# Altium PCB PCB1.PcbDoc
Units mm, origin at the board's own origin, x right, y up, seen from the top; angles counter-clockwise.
Board outline 33.4 x 71.75 mm, 2 copper layers (Top Layer, Bottom Layer), stack 1.586 mm thick; 24 components, 15 nets, 88 pads, 22 vias.
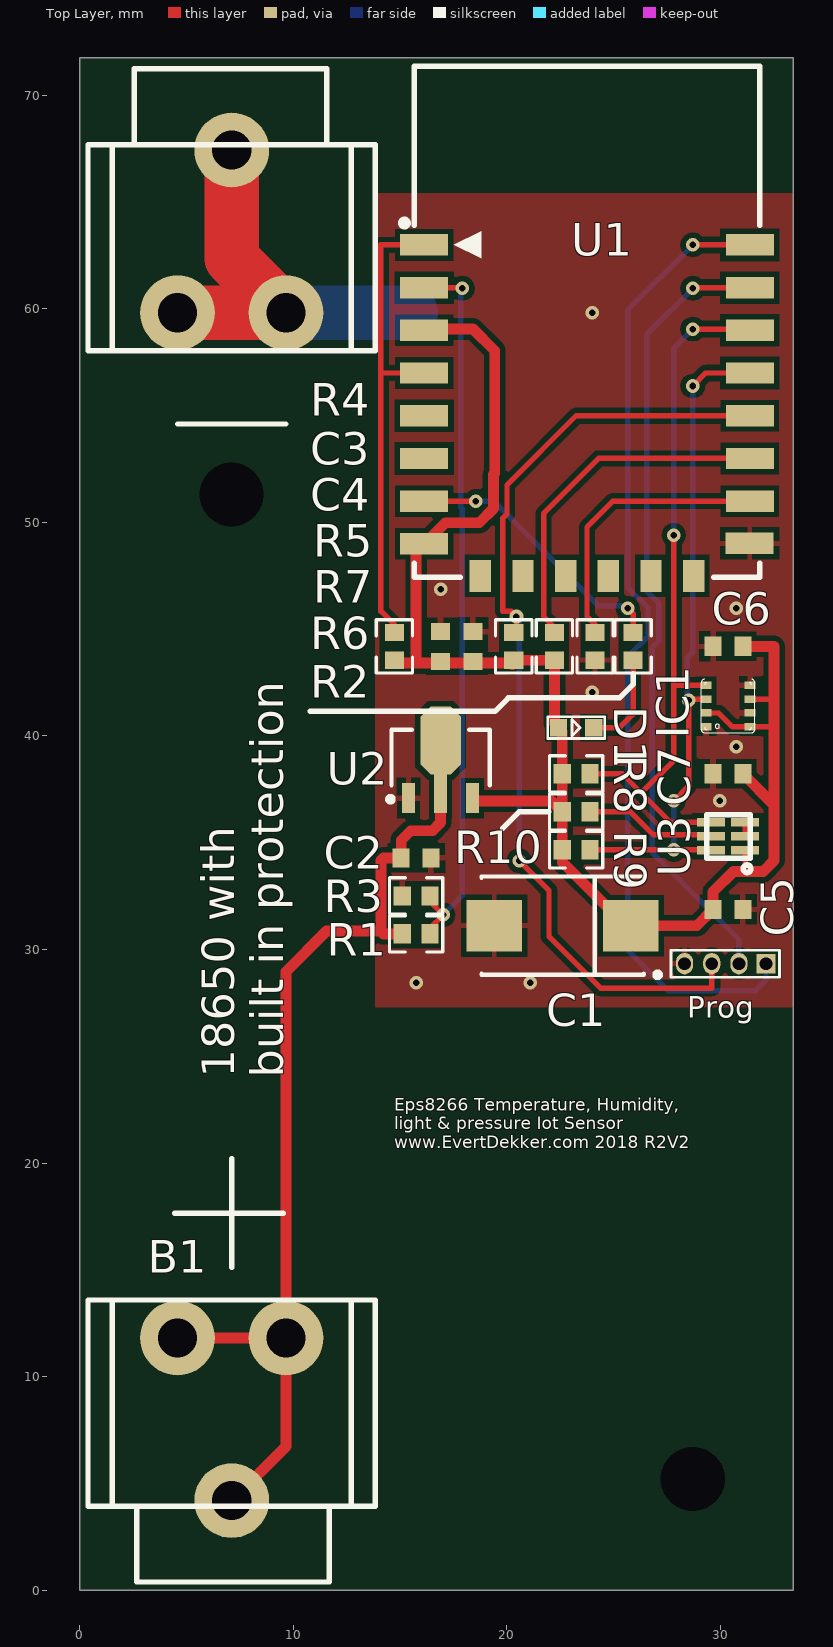
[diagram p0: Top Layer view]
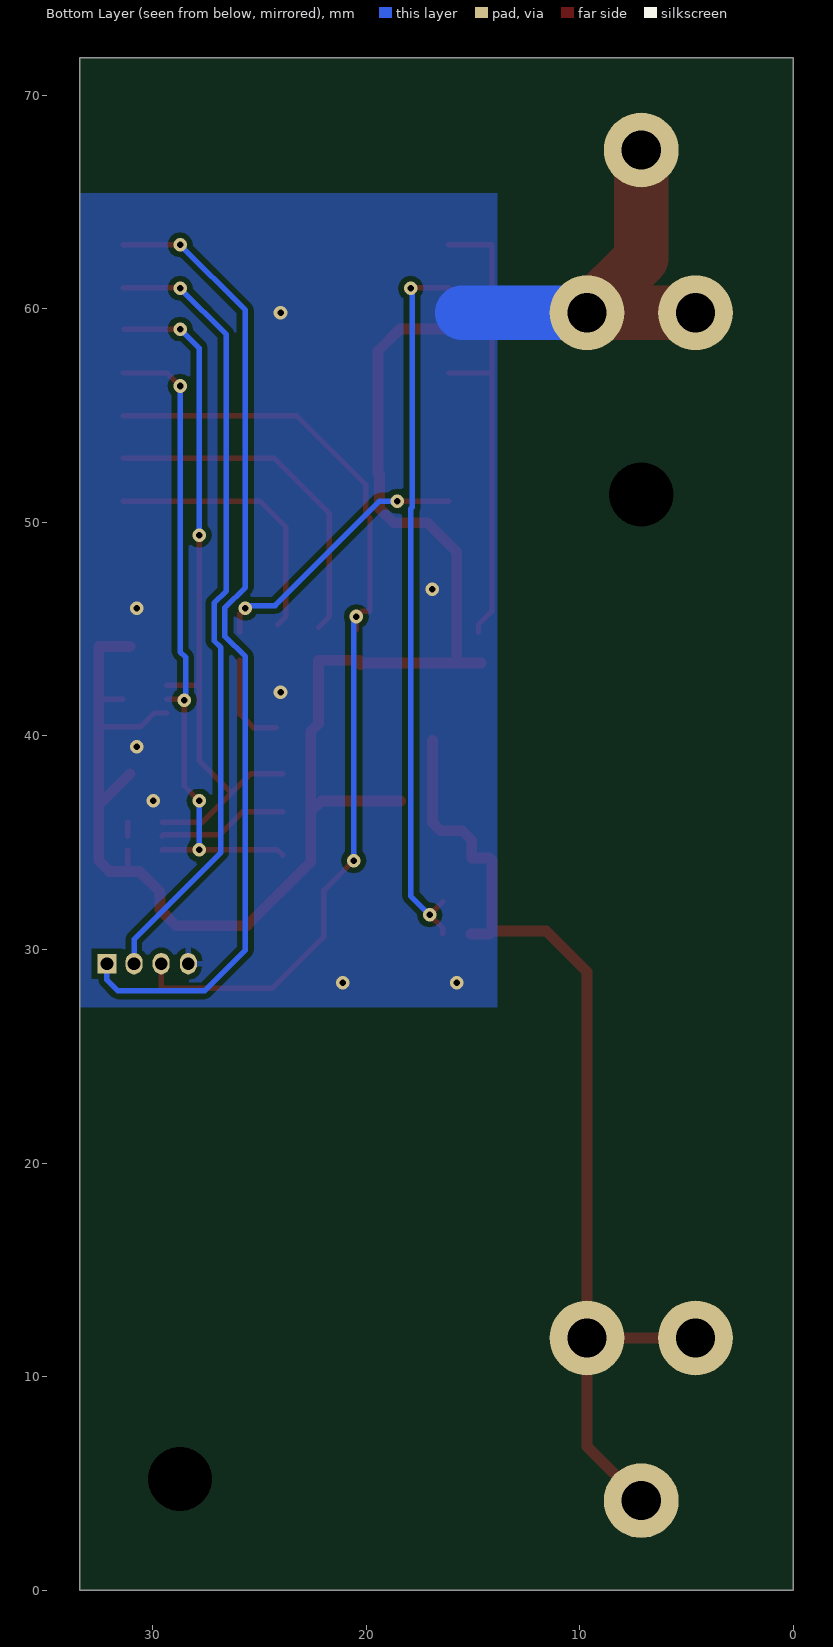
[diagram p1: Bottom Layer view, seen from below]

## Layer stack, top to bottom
Top Solder: solder mask 0.0102, Solder Resist, Dk 3.5
Top Layer: signal copper 0.018
Dielectric1: core 1.55, FR-4, Dk 4.8
Bottom Layer: signal copper 0.018
Bottom Solder: solder mask 0.0102, Solder Resist, Dk 3.5

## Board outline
0,0 0,71.755 33.401,71.755 33.401,0

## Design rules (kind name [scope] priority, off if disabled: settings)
Clearance [All] p1: gap=0.254 except(0.229: Arc-SMDPad SMDPad-SMDPad)
MinimumSolderMaskSliver SilkscreenOverComponentPads_1 [All] p2: minsoldermaskwidth=0.254
MinimumSolderMaskSliver SilkToSolderMaskClearance [IsPad] p3: minsoldermaskwidth=0.254
MinimumSolderMaskSliver SilkscreenOverComponentPads [All] p4: minsoldermaskwidth=0.254
PolygonConnect [IsVia AND InNet('GND')] p1: connectstyle=Direct reliefconductorwidth=0.254 reliefentries=4 polygonreliefangle="90 Angle" airgapwidth=0.254
PolygonConnect PolygonConnect_1 [All] p2: connectstyle=Relief reliefconductorwidth=0.254 reliefentries=4 polygonreliefangle="90 Angle" airgapwidth=0.254
RoutingVias [All] p1: holewidth=0.305 width=0.635 viastyle="Through Hole" minholewidth=0.305 minwidth=0.635 maxholewidth=0.711 maxwidth=1.27
SilkToSolderMaskClearance SilkToSolderMaskClearance_1 [IsPad] p1: minsilkscreentomaskgap=0.254 clearancetoexposedcopper=TRUE
SolderMaskExpansion [All] p1: expansion=0.102
Width [All] p1: maxlimit=2.54 minlimit=0.152 preferedwidth=0.254
29 further rules are at their usual default settings.

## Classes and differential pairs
component class Sheet1: R1 R2 R3 R4 R5 R6

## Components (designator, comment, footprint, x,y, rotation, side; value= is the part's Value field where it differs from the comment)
B1 "KeyStone54" KEYSTONE54_18650 7.112,35.814 r90 top
C1 "T491X" X 22.606,31.115 r180 top
C2 "Cap Semi" 1608[0603] 15.748,34.29 r180 top
C3 "Cap Semi" 1608[0603] 16.891,44.196 r270 top
C4 "Cap Semi" 1608[0603] 18.415,44.196 r270 top
C5 "Cap Semi" 1608[0603] 30.353,31.877 r180 top
C6 "Cap Semi" 1608[0603] 30.353,44.196 r0 top
C7 "Cap Semi" 1608[0603] 30.353,38.227 r0 top
D1 "Led" LED1608 23.241,40.386 r0 top
IC1 "BME280" BME280 30.353,41.402 r270 top
Prog "Prog" Header4x1.27mm 32.131,29.337 r180 top (schematic designator P3)
R1 "Resistor" RES0603R 15.748,30.734 r0 top
R2 "Resistor" RES0603R 25.908,44.196 r90 top
R3 "Resistor" RES0603R 15.748,32.512 r180 top
R4 "Resistor" RES0603R 14.732,44.196 r90 top
R5 "Resistor" RES0603R 20.32,44.196 r90 top
R6 "Resistor" RES0603R 24.13,44.196 r270 top
R7 "Resistor" RES0603R 22.225,44.196 r90 top
R8 "Resistor" RES0603R 23.241,38.227 r0 top
R9 "Resistor" RES0603R 23.241,34.671 r0 top
R10 "Resistor" RES0603R 23.241,36.449 r0 top
U1 "ESP_12_E" ESP_12_E 23.749,55.245 r0 top
U2 "HT7333-SOT89" SOT89_N 16.891,38.989 r90 top
U3 "TSL2561" DFN6-2x2 30.353,35.306 r180 top

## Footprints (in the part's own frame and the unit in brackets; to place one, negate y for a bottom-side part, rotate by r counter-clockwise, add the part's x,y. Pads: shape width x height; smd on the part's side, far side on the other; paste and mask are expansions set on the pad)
1608[0603] [mm] "Chip Capacitor, Body 1.6x0.8mm, IPC High Density"
  rect 0.8x0.9 smd: 1(-0.7,0) 2(0.7,0)
  body extent -0.87,-0.48 0.87,0.48, height 1.3
BME280 [mm]
  rect 0.35x0.5 smd: 1(0.975,-1.025) 2(0.325,-1.025) 3(-0.325,-1.025) 4(-0.975,-1.025) 5(-0.975,1.025) 6(-0.325,1.025) 7(0.325,1.025) 8(0.975,1.025)
  silkscreen extent -1.25,-1.25 1.25,1.25
DFN6-2x2 [mm] "TSL256x Package FN"
  rect 1.3x0.4 smd: 1(-0.8,0.65) 2(-0.8,0) 3(-0.8,-0.65) 4(0.8,-0.65) 5(0.8,0) 6(0.8,0.65)
  silkscreen extent -1.07,-1 0.99,1.7
ESP_12_E [mm] "ESP-12 Wi-Fi Module by AI-Thinker"
  rect 2.25x1 smd: 1(-7.625,7.75) 2(-7.625,5.75) 3(-7.625,3.75) 4(-7.625,1.75) 5(-7.625,-0.25) 6(-7.625,-2.25) 7(-7.625,-4.25) 8(-7.625,-6.25) 15(7.62,-6.223) 16(7.625,-4.25) 17(7.625,-2.25) 18(7.625,-0.25) 19(7.625,1.75) 20(7.625,3.75) 21(7.625,5.75) 22(7.625,7.75)
  rect 1x1.5 smd: 9(-5,-7.75) 10(-3,-7.75) 11(-1,-7.75) 12(1,-7.75) 13(3,-7.75) 14(5,-7.75)
  silkscreen extent -8.7,-7.82 8.08,16.12, body extent -8,-7.74 8,16.26, height 2.75
Header4x1.27mm [mm]
  rect 0.9x0.9 hole 0.6: 1(0,0)
  oval 0.8x1 hole 0.6: 2(1.27,0) 3(2.54,0) 4(3.81,0)
  silkscreen extent -0.64,-0.64 4.44,0.64
KEYSTONE54_18650 [mm] "Keystone 54 16~19mm Pcb battery clip 18650+pcb"
  round 3.5 hole 1.83: 1(-31.623,0) 1(-24.003,-2.54) 1(-24.003,2.54) 2(24.003,-2.54) 2(24.003,2.54) 2(31.623,0)
  silkscreen extent -35.43,-6.73 35.43,6.73, body extent -35.21,-9.08 35.21,9.08, height 18.32
LED1608 [mm] "1608"
  rect 0.8x0.8 smd: A(-0.826,0) K(0.826,0)
  silkscreen extent -1.33,-0.51 1.33,0.51, body extent -0.8,-0.4 0.8,0.4, height 1.11
RES0603R [mm] "resistor 0603 reflow soldering"
  rect 0.8x0.9 smd: 1(-0.65,0) 2(0.65,0)
  silkscreen extent -1.25,-0.85 1.25,0.85, body extent -0.8,-0.4 0.8,0.4, height 0.45
SOT89_N [mm] "SOT89, 3-Leads, Body 4.5x2.4 mm, Pitch 1.5mm, Lead Span 4.1mm, IPC Medium Density"
  rect 1.4x0.6 smd: 1(-1.9,1.5) 3(-1.9,-1.5)
  rect 1.8x0.6 smd: 2(-1.7,0)
  oct 3.2x1.9 smd: 2(0.8,0)
  silkscreen extent -2.07,-2.3 1.3,2.47, body extent -1.3,-2.3 1.29,2.3, height 1.61
X [mm] "Capacitor, SM Tantalum; Body 7.3 x 4.3 mm (LxW typ)"
  rect 2.6x2.4 smd: 1(-3.2,0) 2(3.2,0)
  silkscreen extent -4.58,-2.3 3.8,2.42

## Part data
C1: "Solid Tantalum Chip Capacitor, Standard T491 Series - Industrial Grade"
C2 C3 C4 C5 C6 C7: "Capacitor (Semiconductor SIM Model)"
IC1: "Integrated pressure, humidity and temperature sensor; 8-pin 2.5x2.5x0.93mm LGA"
Prog: library part Header4x1.27mm
U1: "ESP-12 Wi-Fi Module by AI-Thinker"
U2: "Low Power Consumption LDO, Output Voltage 3.3V, SOT89 Pkg"

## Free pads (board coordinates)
  round 0 hole 3 unplated: 2(7.112,51.308) 3(28.702,5.207)

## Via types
v1: diameter 0.635, hole 0.305, Top Layer to Bottom Layer, 22 vias

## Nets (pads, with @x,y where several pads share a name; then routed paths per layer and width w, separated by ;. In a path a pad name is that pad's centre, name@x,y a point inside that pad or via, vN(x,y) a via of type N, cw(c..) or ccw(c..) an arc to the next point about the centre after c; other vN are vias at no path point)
GND: B1.2 C1.2 C2.1 C3.1 C4.1 C5.1 C6.1 C7.1 IC1.1 IC1.5 IC1.7 Prog.4 R3.2 R6.2 U1.15 U2.1 U3.2 U3.3 | length 20.2
  Top Layer w0.254: U3.2 U3.3
  Top Layer w2.54: B1.2@4.572,59.817 9.652,59.817 7.112,62.357 B1.2@7.112,67.437
  Bottom Layer w2.54: B1.2@9.652,59.817 15.494,59.817
  other v1: 15.748,28.448 21.082,28.448 29.972,36.957 30.734,39.497 24.003,42.037 30.734,45.974 16.891,46.863 24.003,59.817
NetB1_1: B1.1 C2.2 R1.1 U2.2 | length 48.3
  Top Layer w0.508: B1.1@4.572,11.811 B1.1@9.652,11.811 ; B1.1@7.112,4.191 9.652,6.731 B1.1@9.652,11.811 ; R1.1 14.224,30.734 14.097,30.861 ; U2.2@16.891,39.789 16.891,35.941 16.51,35.56 15.494,35.56 15.048,35.114 C2.2 14.224,34.29 14.097,34.163 14.097,30.861 ; B1.1@9.652,11.811 9.652,28.956 11.557,30.861 14.097,30.861
NetD1_2: D1.K R2.1 | length 4.5
  Top Layer w0.254: D1.K@24.194,40.386 25.273,40.386 25.908,41.021 R2.1
NetP3_1: Prog.1 U1.22 | length 46
  Top Layer w0.254: v1(28.705,62.995) U1.22
  Bottom Layer w0.254: v1(28.705,62.995) 25.654,59.944 25.654,46.962 26.607,46.009 26.607,44.669 25.654,43.716 25.654,29.972 27.559,28.067 31.623,28.067 32.131,28.575 Prog.1
NetP3_2: Prog.2 U1.21 | length 37.3
  Top Layer w0.254: v1(28.702,60.96) 28.737,60.995 U1.21
  Bottom Layer w0.254: v1(28.702,60.96) 26.543,58.801 26.543,46.791 27.114,46.22 27.114,44.458 26.797,44.141 26.797,34.544 30.861,30.48 Prog.2
NetP3_3: Prog.3 R5.2 U1.18 | length 45.4
  Top Layer w0.254: R5.2@20.447,44.973 v1(20.447,45.593) 20.193,45.847 19.812,45.847 19.812,50.2 20.002,50.39 20.002,51.752 23.245,54.995 U1.18 ; v1(20.574,34.163) 21.971,32.766 21.971,30.607 24.384,28.194 29.591,28.194 Prog.3
  Bottom Layer w0.254: v1(20.447,45.593) 20.574,45.466 v1(20.574,34.163)
NetR1_2: R1.2 R3.1 U1.2 | length 33.6
  Top Layer w0.254: U1.2 17.872,60.995 v1(17.907,60.96) ; R1.2 16.398,31.003 v1(17.018,31.623) R3.1@16.398,32.243
  Bottom Layer w0.254: v1(17.018,31.623) 17.907,32.512 17.907,50.642 17.843,50.706 17.843,60.896 v1(17.907,60.96)
NetR2_2: R2.2 U1.7 | length 12.8
  Top Layer w0.254: U1.7 v1(18.542,50.995) ; v1(25.654,45.974) 25.908,45.72 R2.2
  Bottom Layer w0.254: v1(18.542,50.995) 19.363,50.995 24.257,46.101 25.527,46.101 v1(25.654,45.974)
NetR4_2: R4.2 U1.1 U1.4 | length 22.4
  Top Layer w0.254: 14.128,56.995 U1.4 ; R4.2 14.732,45.212 14.1,45.844 14.1,62.995 U1.1
NetR6_1: R6.1 U1.16 | length 12.9
  Top Layer w0.254: R6.1@24.13,45.212 23.749,45.593 23.749,49.784 24.96,50.995 U1.16
NetR7_2: R7.2 U1.17 | length 16.3
  Top Layer w0.254: R7.2@22.225,45.085 21.717,45.593 21.717,50.419 24.293,52.995 U1.17
NetR10_2: R10.2 U3.5 | length 6.1
  Top Layer w0.254: R10.2 25.781,36.449 26.86,35.369 29.489,35.369 U3.5
SCL: IC1.4 R8.2 U1.20 U3.4 | length 33.5
  Top Layer w0.254: R8.2 25.4,38.227 27.671,35.956 U3.4 ; 26.289,37.338 27.813,38.862 27.813,42.418 ; v1(27.813,49.403) 27.813,42.418 ; v1(28.702,59.055) U1.20@31.314,59.055 ; IC1.4 27.854,42.377 27.813,42.418
  Bottom Layer w0.254: v1(27.813,49.403) 27.813,58.166 v1(28.702,59.055)
SDA: IC1.3 R9.2 U1.19 U3.6 | length 31.7
  Top Layer w0.254: R9.2@23.891,34.417 24.145,34.671 v1(27.813,34.671) 29.538,34.671 U3.6 ; v1(27.813,36.957) 28.511,37.655 v1(28.511,41.679) 28.56,41.727 IC1.3 ; v1(28.702,56.388) 29.309,56.995 U1.19
  Bottom Layer w0.254: v1(27.813,34.671) v1(27.813,36.957) ; v1(28.511,41.679) 28.471,41.679 28.448,41.656 28.448,43.688 28.702,43.942 v1(28.702,56.388)
VCC: C1.1 C3.2 C4.2 C5.2 C6.2 C7.2 D1.A IC1.2 IC1.6 IC1.8 R4.1 R5.1 R7.1 R8.1 R9.1 R10.1 U1.3 U1.8 U2.3 U3.1 | length 74.3
  Top Layer w0.254: IC1.2 29.916,41.077 30.566,40.427 IC1.8 32.471,40.427 ; 31.153,33.744 U3.1 ; IC1.6 32.456,41.727 32.512,41.783
  Top Layer w0.508: R4.1@14.605,43.419 15.748,43.419 ; U1.3 16.184,59.055 18.415,59.055 19.431,58.039 19.431,52.302 19.367,52.238 19.367,50.653 18.701,49.987 17.116,49.987 U1.8 15.748,48.619 15.748,43.419 ; U2.3@18.391,36.957 22.083,36.957 R10.1 ; R5.1@20.252,43.353 20.066,43.419 15.748,43.419 ; R5.1 R7.1 22.225,40.576 D1.A 22.591,40.211 R8.1 R10.1 ; C7.2 32.512,36.768 ; C6.2 32.512,44.196 32.512,41.783 32.512,36.768 ; R10.1 R9.1 22.591,34.105 25.581,31.115 C1.1 28.891,31.115 C5.2 29.653,32.701 30.607,33.655 32.004,33.655 32.512,34.163 32.512,36.768
pads on no net: U1.5 U1.6 U1.9 U1.10 U1.11 U1.12 U1.13 U1.14

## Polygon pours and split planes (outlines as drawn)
GND on Bottom Layer "Bottom Layer-Gnd" (solid, pour order 0): 13.843,65.405 33.401,65.405 33.401,27.305 13.843,27.305
GND on Top Layer "Top Layer-Gnd" (solid, pour order 2): 13.843,65.405 33.401,65.405 33.401,27.305 13.843,27.305

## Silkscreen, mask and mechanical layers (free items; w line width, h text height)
Top Overlay:
  lines w0.254: 10.795,41.148 19.431,41.148 20.066,41.783 25.273,41.783 25.908,42.418 25.908,42.926 ; 19.812,35.687 20.574,36.449 21.971,36.449
  text "Eps8266 Temperature, Humidity, / light & pressure Iot Sensor / www.EvertDekker.com 2018 R2V2" at 14.732,20.701 h0.58
BoardOutline:
  the board outline again, w0.127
